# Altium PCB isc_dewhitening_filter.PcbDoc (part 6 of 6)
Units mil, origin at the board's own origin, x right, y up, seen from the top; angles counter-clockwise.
Board outline 8440 x 7000 mil, 6 copper layers (Top Layer, MidLayer1, InternalPlane1, Internal Plane 3, InternalPlane2, Bottom Layer); 550 components, 462 nets, 2189 pads, 795 vias.
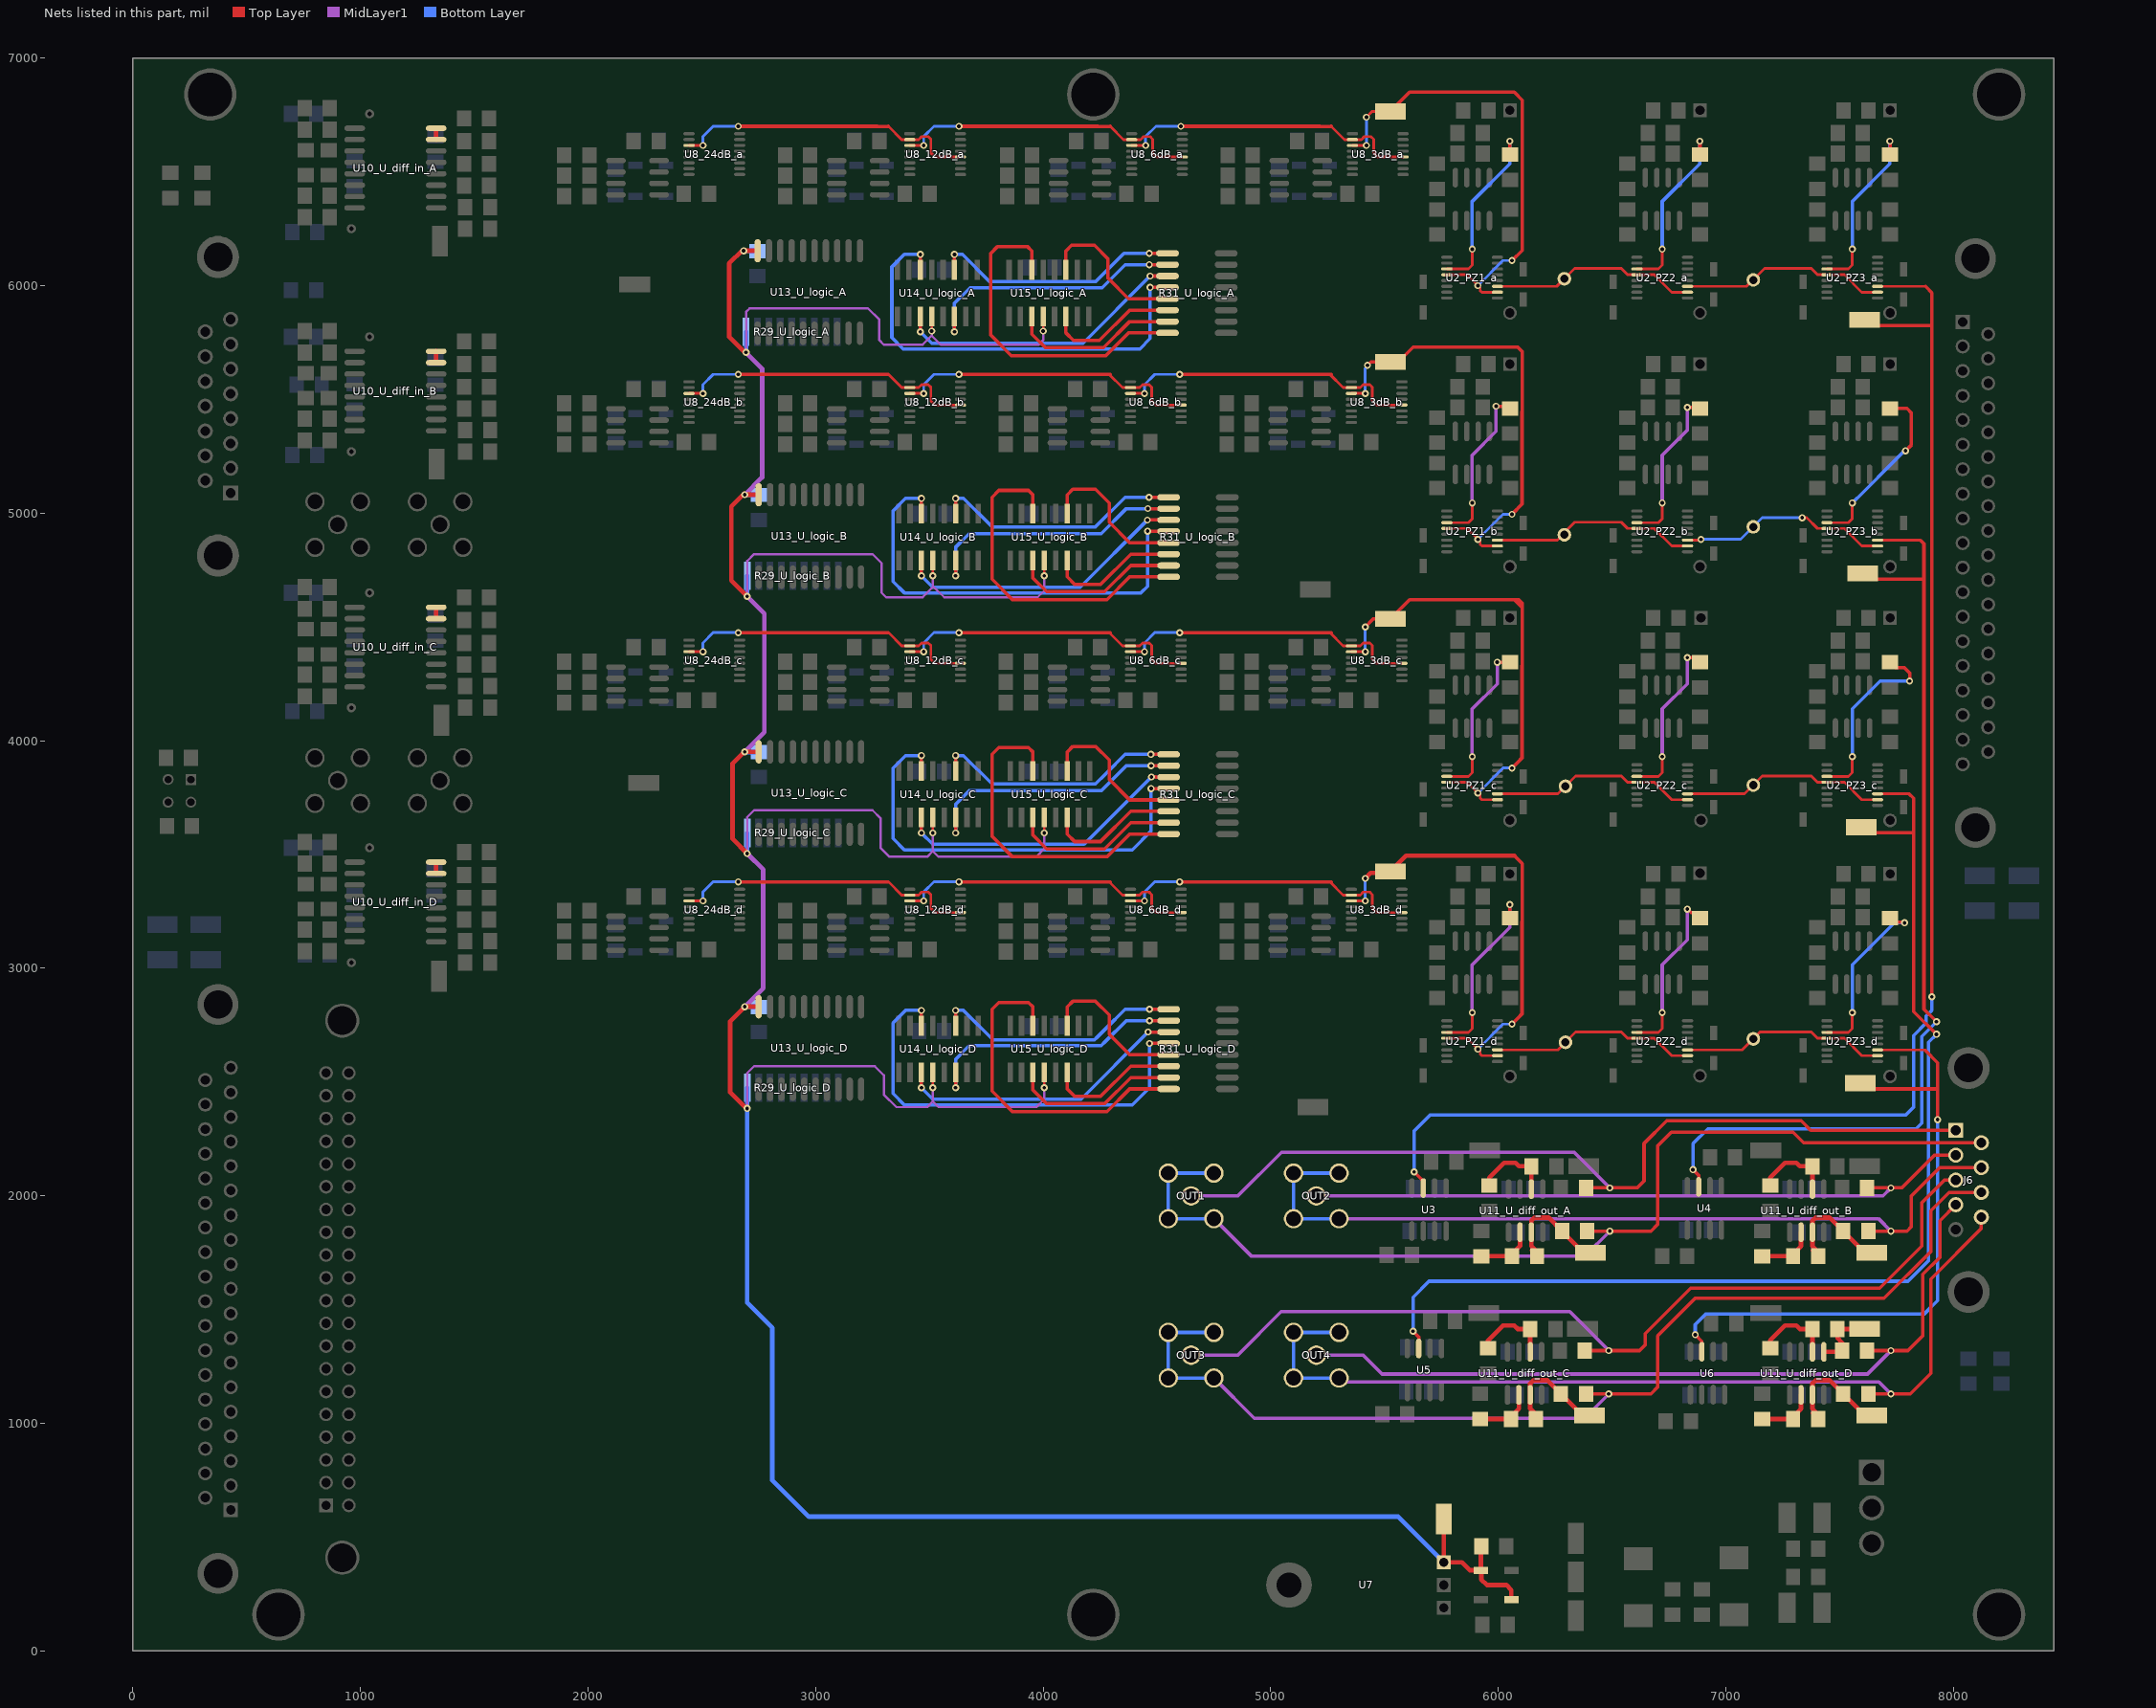
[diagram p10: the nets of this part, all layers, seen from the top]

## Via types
v1: diameter 31, hole 16, Top Layer to Bottom Layer, 794 vias
v2: diameter 45, hole 20, Top Layer to Bottom Layer, 1 vias

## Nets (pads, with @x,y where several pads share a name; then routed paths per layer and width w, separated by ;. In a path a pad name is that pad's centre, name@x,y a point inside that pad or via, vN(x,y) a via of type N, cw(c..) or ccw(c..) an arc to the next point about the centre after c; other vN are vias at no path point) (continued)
NetR23_U_diff_out_D_1: R23_U_diff_out_D.1 R25_U_diff_out_D.2 TP7_U_diff_out_D.1 U11_U_diff_out_D.1 | length 305.2
  Top Layer w15: R23_U_diff_out_D.1@7504.37,1314.49 R23_U_diff_out_D.1@7509.88,1320
  Top Layer w20: U11_U_diff_out_D.1@7430,1314.49 R23_U_diff_out_D.1@7504.37,1314.49 ; R23_U_diff_out_D.1@7509.88,1320 7509.88,1355.12 7490.12,1374.88 R25_U_diff_out_D.2@7490.12,1415 TP7_U_diff_out_D.1@7610,1415
NetR24_U_diff_out_A_2: R24_U_diff_out_A.2 R25_U_diff_out_A.1 U11_U_diff_out_A.2 | length 361.1
  Top Layer w20: R24_U_diff_out_A.2@5960,2045.12 5960,2080 6025,2145 6075,2145 6090,2130 R25_U_diff_out_A.1@6144.88,2130 R25_U_diff_out_A.1@6139.38,2135.5 ; U11_U_diff_out_A.2@6145,2029.49 R25_U_diff_out_A.1@6145,2129.88
NetR24_U_diff_out_B_2: R24_U_diff_out_B.2 R25_U_diff_out_B.1 U11_U_diff_out_B.2 | length 361.1
  Top Layer w20: R24_U_diff_out_B.2@7195,2045.12 7195,2080 7260,2145 7310,2145 7325,2130 R25_U_diff_out_B.1@7379.88,2130 R25_U_diff_out_B.1@7374.38,2135.5 ; U11_U_diff_out_B.2@7380,2029.49 R25_U_diff_out_B.1@7380,2129.88
NetR24_U_diff_out_C_2: R24_U_diff_out_C.2 R25_U_diff_out_C.1 U11_U_diff_out_C.2 | length 361.1
  Top Layer w20: R24_U_diff_out_C.2@5955,1330.12 5955,1365 6020,1430 6070,1430 6085,1415 R25_U_diff_out_C.1@6139.88,1415 R25_U_diff_out_C.1@6134.38,1420.5 ; U11_U_diff_out_C.2@6140,1314.49 R25_U_diff_out_C.1@6140,1414.88
NetR24_U_diff_out_D_2: R24_U_diff_out_D.2 R25_U_diff_out_D.1 U11_U_diff_out_D.2 | length 361.1
  Top Layer w20: R24_U_diff_out_D.2@7195,1330.12 7195,1365 7260,1430 7310,1430 7325,1415 R25_U_diff_out_D.1@7379.88,1415 R25_U_diff_out_D.1@7374.38,1420.5 ; U11_U_diff_out_D.2@7380,1314.49 R25_U_diff_out_D.1@7380,1414.88
NetR26_U_diff_out_A_1: R26_U_diff_out_A.1 R28_U_diff_out_A.2 TP9_U_diff_out_A.1 U11_U_diff_out_A.7 | length 531.2
  Top Layer w15: R28_U_diff_out_A.2@6145,1760.12 6170,1735.12 R28_U_diff_out_A.2@6170.12,1735
  Top Layer w20: R28_U_diff_out_A.2@6170,1735.12 6170,1755 6145,1780 U11_U_diff_out_A.7@6145,1840.51 6145,1890 6160,1905 6219.88,1905 R26_U_diff_out_A.1@6279.88,1845 6374.88,1750 TP9_U_diff_out_A.1@6405,1750
NetR26_U_diff_out_B_1: R26_U_diff_out_B.1 R28_U_diff_out_B.2 TP9_U_diff_out_B.1 U11_U_diff_out_B.7 | length 531.2
  Top Layer w15: R28_U_diff_out_B.2@7380,1760.12 7405,1735.12 R28_U_diff_out_B.2@7405.12,1735
  Top Layer w20: R28_U_diff_out_B.2@7405,1735.12 7405,1755 7380,1780 U11_U_diff_out_B.7@7380,1840.51 7380,1890 7395,1905 7454.88,1905 R26_U_diff_out_B.1@7514.88,1845 7609.88,1750 TP9_U_diff_out_B.1@7640,1750
NetR26_U_diff_out_C_1: R26_U_diff_out_C.1 R28_U_diff_out_C.2 TP9_U_diff_out_C.1 U11_U_diff_out_C.7 | length 531.2
  Top Layer w15: R28_U_diff_out_C.2@6140,1045.12 6165,1020.12 R28_U_diff_out_C.2@6165.12,1020
  Top Layer w20: R28_U_diff_out_C.2@6165,1020.12 6165,1040 6140,1065 U11_U_diff_out_C.7@6140,1125.51 6140,1175 6155,1190 6214.88,1190 R26_U_diff_out_C.1@6274.88,1130 6369.88,1035 TP9_U_diff_out_C.1@6400,1035
NetR26_U_diff_out_D_1: R26_U_diff_out_D.1 R28_U_diff_out_D.2 TP9_U_diff_out_D.1 U11_U_diff_out_D.7 | length 531.2
  Top Layer w15: R28_U_diff_out_D.2@7380,1045.12 7405,1020.12 R28_U_diff_out_D.2@7405.12,1020
  Top Layer w20: R28_U_diff_out_D.2@7405,1020.12 7405,1040 7380,1065 U11_U_diff_out_D.7@7380,1125.51 7380,1175 7395,1190 7454.88,1190 R26_U_diff_out_D.1@7514.88,1130 7609.88,1035 TP9_U_diff_out_D.1@7640,1035
NetR27_U_diff_out_A_2: R27_U_diff_out_A.2 R28_U_diff_out_A.1 U11_U_diff_out_A.6 | length 249.2
  Top Layer w20: R27_U_diff_out_A.2@5925,1734.88 6049.88,1734.88 6095,1780 U11_U_diff_out_A.6@6095,1840.51
NetR27_U_diff_out_B_2: R27_U_diff_out_B.2 R28_U_diff_out_B.1 U11_U_diff_out_B.6 | length 249.2
  Top Layer w20: R27_U_diff_out_B.2@7160,1734.88 7284.88,1734.88 7330,1780 U11_U_diff_out_B.6@7330,1840.51
NetR27_U_diff_out_C_2: R27_U_diff_out_C.2 R28_U_diff_out_C.1 U11_U_diff_out_C.6 | length 249.2
  Top Layer w20: R27_U_diff_out_C.2@5920,1019.88 6044.88,1019.88 6090,1065 U11_U_diff_out_C.6@6090,1125.51
NetR27_U_diff_out_D_2: R27_U_diff_out_D.2 R28_U_diff_out_D.1 U11_U_diff_out_D.6 | length 249.2
  Top Layer w20: R27_U_diff_out_D.2@7160,1019.88 7284.88,1019.88 7330,1065 U11_U_diff_out_D.6@7330,1125.51
NetR30_PZ1_a_2: R30_PZ1_a.2 U2_PZ1_a.3 | length 791.7
  Top Layer w12: U2_PZ1_a.3@5773.78,6073.39 5868.39,6073.39 5885,6090 v1(5885,6160)
  Top Layer w15: v1(6050,6635) 6051,6634 R30_PZ1_a.2@6051,6575.12
  Bottom Layer w15: v1(5885,6160) 5885,6370 6050,6535 v1(6050,6635)
NetR30_PZ1_b_2: R30_PZ1_b.2 U2_PZ1_b.3 | length 721.7
  Top Layer w12: U2_PZ1_b.3@5773.78,4958.39 5868.39,4958.39 5885,4975 v1(5885,5045)
  Top Layer w15: v1(5990,5470) 5990.54,5469.46 6041.66,5469.46 R30_PZ1_b.2@6051,5460.12
  MidLayer1 w15: v1(5885,5045) 5885,5255 5990,5360 v1(5990,5470)
NetR30_PZ1_c_2: R30_PZ1_c.2 U2_PZ1_c.3 | length 704.7
  Top Layer w12: U2_PZ1_c.3@5773.78,3843.39 5868.39,3843.39 5885,3860 v1(5885,3930)
  Top Layer w15: v1(5995,4345) 6050.88,4345 R30_PZ1_c.2@6051,4345.12
  MidLayer1 w15: v1(5885,3930) 5885,4140 5995,4250 v1(5995,4345)
NetR30_PZ1_d_2: R30_PZ1_d.2 U2_PZ1_d.3 | length 791.7
  Top Layer w12: U2_PZ1_d.3@5773.78,2718.39 5868.39,2718.39 5885,2735 v1(5885,2805)
  Top Layer w15: v1(6050,3280) 6051,3279 R30_PZ1_d.2@6051,3220.12
  MidLayer1 w15: v1(5885,2805) 5885,3015 6050,3180 v1(6050,3280)
NetR30_PZ2_a_2: R30_PZ2_a.2 U2_PZ2_a.3 | length 791.7
  Top Layer w12: U2_PZ2_a.3@6608.78,6073.39 6703.39,6073.39 6720,6090 v1(6720,6160)
  Top Layer w15: v1(6885,6635) 6886,6634 R30_PZ2_a.2@6886,6575.12
  Bottom Layer w15: v1(6720,6160) 6720,6370 6885,6535 v1(6885,6635)
NetR30_PZ2_b_2: R30_PZ2_b.2 U2_PZ2_b.3 | length 711.7
  Top Layer w12: U2_PZ2_b.3@6608.78,4958.39 6703.39,4958.39 6720,4975 v1(6720,5045)
  Top Layer w15: v1(6830,5465) 6881.12,5465 R30_PZ2_b.2@6886,5460.12
  MidLayer1 w15: v1(6720,5045) 6720,5255 6830,5365 v1(6830,5465)
NetR30_PZ2_c_2: R30_PZ2_c.2 U2_PZ2_c.3 | length 732.9
  Top Layer w12: U2_PZ2_c.3@6608.78,3843.39 6703.39,3843.39 6720,3860 v1(6720,3930)
  Top Layer w15: v1(6830,4365) 6866.12,4365 R30_PZ2_c.2@6886,4345.12
  MidLayer1 w15: v1(6720,3930) 6720,4140 6830,4250 v1(6830,4365)
NetR30_PZ2_d_2: R30_PZ2_d.2 U2_PZ2_d.3 | length 761.2
  Top Layer w12: U2_PZ2_d.3@6608.78,2718.39 6703.39,2718.39 6720,2735 v1(6720,2805)
  Top Layer w15: v1(6830,3260) 6830.9,3260 6846.79,3244.11 6862,3244.11 R30_PZ2_d.2@6886,3220.12
  MidLayer1 w15: v1(6720,2805) 6720,3015 6830,3125 v1(6830,3260)
NetR30_PZ3_a_2: R30_PZ3_a.2 U2_PZ3_a.3 | length 791.7
  Top Layer w12: U2_PZ3_a.3@7443.78,6073.39 7538.39,6073.39 7555,6090 v1(7555,6160)
  Top Layer w15: v1(7720,6635) 7721,6634 R30_PZ3_a.2@7721,6575.12
  Bottom Layer w15: v1(7555,6160) 7555,6370 7720,6535 v1(7720,6635)
NetR30_PZ3_b_2: R30_PZ3_b.2 U2_PZ3_b.3 | length 824.3
  Top Layer w12: U2_PZ3_b.3@7443.78,4958.39 7538.39,4958.39 7555,4975 v1(7555,5045)
  Top Layer w15: R30_PZ3_b.2@7721,5460.12 7794.88,5460.12 7815,5440 7815,5300 v1(7789,5274)
  Bottom Layer w15: 7575,5065 v1(7555,5045) 7776,5266 7776.67,5266 7784.67,5274 v1(7789,5274)
NetR30_PZ3_c_2: R30_PZ3_c.2 U2_PZ3_c.3 | length 842.2
  Top Layer w12: U2_PZ3_c.3@7443.78,3843.39 7538.39,3843.39 7555,3860 v1(7555,3930)
  Top Layer w15: R30_PZ3_c.2@7721,4345.12 7745,4321.12 7783.88,4321.12 7807,4298 v1(7807,4262)
  Bottom Layer w15: v1(7555,3930) 7555,4140 7677,4262 v1(7807,4262)
NetR30_PZ3_d_2: R30_PZ3_d.2 U2_PZ3_d.3 | length 777.1
  Top Layer w12: U2_PZ3_d.3@7443.78,2718.39 7538.39,2718.39 7555,2735 v1(7555,2805)
  Top Layer w15: R30_PZ3_d.2@7721,3220.12 7737.58,3203.54 7777.13,3203.54 7780.67,3200 v1(7785,3200)
  Bottom Layer w15: v1(7555,2805) 7555,3015 7740,3200 v1(7785,3200)
NetR31_U_logic_A_1: R31_U_logic_A.1 U14_U_logic_A.3 | length 1104.4
  Top Layer w15: U14_U_logic_A.3@3610,6069.36 v1(3610,6137) ; v1(4466,6142) R31_U_logic_A.1@4546.06,6142
  Bottom Layer w15: v1(3610,6137) 3645,6137 3764,6018 4231,6018 4355,6142 v1(4466,6142)
NetR31_U_logic_A_2: R31_U_logic_A.2 U14_U_logic_A.14 | length 1199.1
  Top Layer w15: v1(3610,5797) U14_U_logic_A.14@3610,5864.64 ; v1(4466,6092) R31_U_logic_A.2@4546.06,6092
  Bottom Layer w15: v1(3610,5797) 3610,5922 3678.43,5990.43 4258.43,5990.43 4360,6092 v1(4466,6092)
NetR31_U_logic_A_3: R31_U_logic_A.3 U14_U_logic_A.11 | length 1296.6
  Top Layer w15: v1(3460,5797) U14_U_logic_A.11@3460,5864.64 ; v1(4470,6042) R31_U_logic_A.3@4546.06,6042
  Bottom Layer w15: v1(3460,5797) 3510,5747 4175,5747 v1(4470,6042)
NetR31_U_logic_A_4: R31_U_logic_A.4 U14_U_logic_A.6 | length 2033.3
  Top Layer w15: U14_U_logic_A.6@3460,6069.36 v1(3460,6137) ; v1(4470,5992) R31_U_logic_A.4@4578.54,5992
  Bottom Layer w15: v1(3460,6137) 3390,6137 3335,6082 3335,5772 3385,5722 4425,5722 4470,5767 v1(4470,5992)
NetR31_U_logic_A_5: R31_U_logic_A.5 U15_U_logic_A.3 | length 718.7
  Top Layer w15: U15_U_logic_A.3@4100,6069.36 4100,6152 4125,6177 4225,6177 4285,6117 4285,6032 4375,5942 R31_U_logic_A.5@4578.54,5942
NetR31_U_logic_A_6: R31_U_logic_A.6 U15_U_logic_A.14 | length 619.9
  Top Layer w15: U15_U_logic_A.14@4100,5864.64 4100,5792 4133,5759 4247,5759 4380,5892 R31_U_logic_A.6@4578.54,5892
NetR31_U_logic_A_7: R31_U_logic_A.7 U15_U_logic_A.11 | length 778.7
  Top Layer w15: U15_U_logic_A.11@3950,5864.64 3950,5787 4010,5727 4265,5727 4380,5842 R31_U_logic_A.7@4578.54,5842
NetR31_U_logic_A_8: R31_U_logic_A.8 U15_U_logic_A.6 | length 1530.6
  Top Layer w15: U15_U_logic_A.6@3950,6069.36 3950,6152 3930,6172 3830,6172 3800,6172 3770,6142 3770,5782 3860,5692 4275,5692 4375,5792 R31_U_logic_A.8@4578.54,5792
NetR31_U_logic_B_1: R31_U_logic_B.1 U14_U_logic_B.3 | length 1104.3
  Top Layer w15: U14_U_logic_B.3@3615,4997.36 v1(3615,5065) ; v1(4465,5070) R31_U_logic_B.1@4551.06,5070
  Bottom Layer w15: v1(3615,5065) 3650,5065 3775,4940 4230,4940 4360,5070 v1@4460,5070
NetR31_U_logic_B_2: R31_U_logic_B.2 U14_U_logic_B.14 | length 1199.1
  Top Layer w15: v1(3615,4725) U14_U_logic_B.14@3615,4792.64 ; v1(4460,5020) R31_U_logic_B.2@4551.06,5020
  Bottom Layer w15: v1(3615,4725) 3615,4850 3675,4910 4255,4910 4365,5020 v1(4460,5020)
NetR31_U_logic_B_3: R31_U_logic_B.3 U14_U_logic_B.11 | length 1329.1
  Top Layer w15: v1(3465,4725) U14_U_logic_B.11@3465,4792.64 ; v1(4458,4970) R31_U_logic_B.3@4583.54,4970
  Bottom Layer w15: v1(3465,4725) 3515,4675 4163,4675 v1(4458,4970)
NetR31_U_logic_B_4: R31_U_logic_B.4 U14_U_logic_B.6 | length 2043.7
  Top Layer w15: U14_U_logic_B.6@3465,4997.36 v1(3465,5065) ; v1@4459,4920 R31_U_logic_B.4@4583.54,4920
  Bottom Layer w15: v1(3465,5065) 3395,5065 3340,5010 3340,4700 3390,4650 4430,4650 4459,4679 v1(4459,4921)
NetR31_U_logic_B_5: R31_U_logic_B.5 U15_U_logic_B.3 | length 718.7
  Top Layer w15: U15_U_logic_B.3@4105,4997.36 4105,5080 4130,5105 4230,5105 4290,5045 4290,4960 4380,4870 R31_U_logic_B.5@4583.54,4870
NetR31_U_logic_B_6: R31_U_logic_B.6 U15_U_logic_B.14 | length 619.9
  Top Layer w15: U15_U_logic_B.14@4105,4792.64 4105,4720 4138,4687 4252,4687 4385,4820 R31_U_logic_B.6@4583.54,4820
NetR31_U_logic_B_7: R31_U_logic_B.7 U15_U_logic_B.11 | length 778.7
  Top Layer w15: U15_U_logic_B.11@3955,4792.64 3955,4715 4015,4655 4270,4655 4385,4770 R31_U_logic_B.7@4583.54,4770
NetR31_U_logic_B_8: R31_U_logic_B.8 U15_U_logic_B.6 | length 1530.6
  Top Layer w15: U15_U_logic_B.6@3955,4997.36 3955,5080 3935,5100 3835,5100 3805,5100 3775,5070 3775,4710 3865,4620 4280,4620 4380,4720 R31_U_logic_B.8@4583.54,4720
NetR31_U_logic_C_1: R31_U_logic_C.1 U14_U_logic_C.3 | length 1141.8
  Top Layer w15: U14_U_logic_C.3@3615,3867.36 v1(3615,3935) ; v1(4473,3940) R31_U_logic_C.1@4583.54,3940
  Bottom Layer w15: v1(3615,3935) 3650,3935 3775,3810 4230,3810 4275,3855 4360,3940 v1(4473,3940)
NetR31_U_logic_C_2: R31_U_logic_C.2 U14_U_logic_C.14 | length 1231.6
  Top Layer w15: v1(3615,3595) U14_U_logic_C.14@3615,3662.64 ; v1(4474,3890) R31_U_logic_C.2@4583.54,3890
  Bottom Layer w15: v1(3615,3595) 3615,3720 3675,3780 4255,3780 4273,3798 4365,3890 v1(4474,3890)
NetR31_U_logic_C_3: R31_U_logic_C.3 U14_U_logic_C.11 | length 1329.9
  Top Layer w15: v1(3465,3595) U14_U_logic_C.11@3465,3662.64 ; v1(4476,3841) 4494,3841 4495,3840 R31_U_logic_C.3@4583.54,3840
  Bottom Layer w15: v1(3465,3595) 3515,3545 4180,3545 v1(4476,3841)
NetR31_U_logic_C_4: R31_U_logic_C.4 U14_U_logic_C.6 | length 2011.1
  Top Layer w15: U14_U_logic_C.6@3465,3867.36 v1(3465,3935) ; v1(4474,3790) R31_U_logic_C.4@4583.54,3790
  Bottom Layer w15: v1(3465,3935) 3395,3935 3340,3880 3340,3570 3390,3520 4391,3520 4474,3603 v1(4474,3790)
NetR31_U_logic_C_5: R31_U_logic_C.5 U15_U_logic_C.3 | length 718.7
  Top Layer w15: U15_U_logic_C.3@4105,3867.36 4105,3950 4130,3975 4230,3975 4290,3915 4290,3830 4380,3740 R31_U_logic_C.5@4583.54,3740
NetR31_U_logic_C_6: R31_U_logic_C.6 U15_U_logic_C.14 | length 619.9
  Top Layer w15: U15_U_logic_C.14@4105,3662.64 4105,3590 4138,3557 4252,3557 4385,3690 R31_U_logic_C.6@4583.54,3690
NetR31_U_logic_C_7: R31_U_logic_C.7 U15_U_logic_C.11 | length 778.7
  Top Layer w15: U15_U_logic_C.11@3955,3662.64 3955,3585 4015,3525 4270,3525 4385,3640 R31_U_logic_C.7@4583.54,3640
NetR31_U_logic_C_8: R31_U_logic_C.8 U15_U_logic_C.6 | length 1530.6
  Top Layer w15: U15_U_logic_C.6@3955,3867.36 3955,3950 3935,3970 3835,3970 3805,3970 3775,3940 3775,3580 3865,3490 4280,3490 4380,3590 R31_U_logic_C.8@4583.54,3590
NetR31_U_logic_D_1: R31_U_logic_D.1 U14_U_logic_D.3 | length 1145.9
  Top Layer w15: U14_U_logic_D.3@3615,2747.36 v1(3615,2815) ; v1(4467,2820) R31_U_logic_D.1@4583.54,2820
  Bottom Layer w15: v1(3615,2815) 3650,2815 3780,2685 4225,2685 4235,2695 4275,2735 4360,2820 v1(4467,2820)
NetR31_U_logic_D_2: R31_U_logic_D.2 U14_U_logic_D.14 | length 1231.6
  Top Layer w15: v1(3615,2475) U14_U_logic_D.14@3615,2542.64 ; v1(4467,2770) R31_U_logic_D.2@4583.54,2770
  Bottom Layer w15: v1(3615,2475) 3615,2600 3675,2660 4255,2660 4273,2678 4365,2770 v1(4467,2770)
NetR31_U_logic_D_3: R31_U_logic_D.3 U14_U_logic_D.11 | length 1329.1
  Top Layer w15: v1(3465,2475) U14_U_logic_D.11@3465,2542.64 ; v1(4461,2720) R31_U_logic_D.3@4583.54,2720
  Bottom Layer w15: v1(3465,2475) 3515,2425 4166,2425 v1(4461,2720)
NetR31_U_logic_D_4: R31_U_logic_D.4 U14_U_logic_D.6 | length 1983.3
  Top Layer w15: U14_U_logic_D.6@3465,2747.36 v1(3465,2815) ; v1(4467,2670) R31_U_logic_D.4@4551.06,2670
  Bottom Layer w15: v1(3465,2815) 3395,2815 3340,2760 3340,2450 3390,2400 4392,2400 4467,2475 v1(4467,2670)
NetR31_U_logic_D_5: R31_U_logic_D.5 U15_U_logic_D.3 | length 718.7
  Top Layer w15: U15_U_logic_D.3@4105,2747.36 4105,2830 4130,2855 4230,2855 4290,2795 4290,2710 4380,2620 R31_U_logic_D.5@4583.54,2620
NetR31_U_logic_D_6: R31_U_logic_D.6 U15_U_logic_D.14 | length 619.9
  Top Layer w15: U15_U_logic_D.14@4105,2542.64 4105,2470 4138,2437 4252,2437 4385,2570 R31_U_logic_D.6@4583.54,2570
NetR31_U_logic_D_7: R31_U_logic_D.7 U15_U_logic_D.11 | length 778.7
  Top Layer w15: U15_U_logic_D.11@3955,2542.64 3955,2465 4015,2405 4270,2405 4385,2520 R31_U_logic_D.7@4583.54,2520
NetR31_U_logic_D_8: R31_U_logic_D.8 U15_U_logic_D.6 | length 1530.6
  Top Layer w15: U15_U_logic_D.6@3955,2747.36 3955,2830 3935,2850 3835,2850 3805,2850 3775,2820 3775,2460 3865,2370 4280,2370 4380,2470 R31_U_logic_D.8@4583.54,2470
NetTP2_1: TP2.1 U2_PZ1_a.4 U2_PZ1_a.10 U8_3dB_a.11 | length 2110.5
  Top Layer w12: U8_3dB_a.11@5358.78,6616.18 v1(5420,6616.18) ; v1(5420,6740) 5445,6765 TP2.1@5525,6765 ; U2_PZ1_a.4@5773.78,6047.8 5862.2,6047.8 v1(5910,6000) 5920,5990 5920,5978.05 5927.03,5971.02 U2_PZ1_a.10@5996.22,5971.02
  Top Layer w15: TP2.1@5525,6765 5610,6850 6070,6850 6105,6815 6105,6155 v1(6060,6110)
  Bottom Layer w12: v1(5420,6616.18) v1(5420,6740) ; v1(5910,6000) 6020,6110 v1(6060,6110)
NetTP13_1: TP13.1 U2_PZ3_a.11 U3.3 | length 6672.8
  Top Layer w12: U2_PZ3_a.11@7666.22,5996.61 7876.61,5996.61
  Top Layer w15: v1(5630,2105) 5670,2065 U3.3@5670,2034.49 ; TP13.1@7610,5850 7635,5825 7905,5825 ; 7876.61,5996.61 7905,5968.23 7905,5825.3 v1(7905,2875)
  Bottom Layer w15: v1(5630,2105) 5630,2285 5700,2355 7790,2355 7825,2390 7825,2705 7880,2760 7880,2790 7905,2815 v1(7905,2875)
NetTP15_1: TP15.1 U2_PZ1_b.4 U2_PZ1_b.10 U8_3dB_b.11 | length 2758.1
  Top Layer w12: U8_3dB_b.11@5353.78,5526.18 v1(5415,5526.18) ; U2_PZ1_b.4@5773.78,4932.8 5862.2,4932.8 v1(5910,4885) 5920,4875 5920,4863.05 5927.03,4856.02 U2_PZ1_b.10@5996.22,4856.02
  Top Layer w15: v1(5425,5650) 5426.18,5650 5441.18,5665 TP15.1@5525,5665 5560,5665 5625,5730 6085,5730 6105,5710 6105,5476.24 ; v1(6060,4995) 6105,5040 6105,5700 ; 6084,5020 6104,5040 6104,5445
  Bottom Layer w12: v1(5415,5526.18) 5415,5634.86 5425,5644.86 v1(5425,5650) ; v1(5910,4885) 6020,4995 v1(6060,4995)
NetTP16_1: TP16.1 U2_PZ3_b.11 U4.3 | length 4323.2
  Top Layer w12: U2_PZ3_b.11@7666.22,4881.61 7855,4881.61
  Top Layer w15: v1@6860,2115 v1(6855,2115) 6880,2090 U4.3@6880,2039.49 ; TP16.1@7610,4735 7635,4710 7870,4710 ; 7855,4880 7870,4865 7870,4710 ; v1(7925,2765) 7870,2820 7870,3766.61 7870,4710
  Bottom Layer w15: v1(6855,2115) 6855,2230 6920,2295 7835,2295 7860,2320 7860,2700 v1(7925,2765)
NetTP18_1: TP18.1 U2_PZ1_c.4 U2_PZ1_c.10 U8_3dB_c.11 | length 2814.2
  Top Layer w12: U8_3dB_c.11@5353.78,4391.18 v1(5415,4391.18) ; U2_PZ1_c.4@5773.78,3817.8 5862.2,3817.8 v1(5910,3770) 5920,3760 5920,3748.05 5927.03,3741.02 U2_PZ1_c.10@5996.22,3741.02
  Top Layer w15: v1(5415,4500) 5450,4535 TP18.1@5525,4535 5610,4620 6090,4620 6105,4605 6105,4370 ; v1(6060,3880) 6105,3925 6105,4585 6070,4620 ; 6084,3905 6104,3925 6104,4330
  Bottom Layer w12: v1(5415,4391.18) v1(5415,4500) ; v1(5910,3770) 6020,3880 v1(6060,3880)
NetTP19_1: TP19.1 U2_PZ3_c.11 U5.3 | length 5047.1
  Top Layer w12: U2_PZ3_c.11@7666.22,3766.61 7805,3766.61
  Top Layer w15: v1(5625,1405) 5650,1380 U5.3@5650,1329.49 ; TP19.1@7610,3620 7635,3595 7825,3595 ; 7805,3766.61 7825,3746.61 7825,3595 ; v1(7925,2710) 7825,2810 7825,3595
  Bottom Layer w15: v1(5625,1405) 5625,1555 5695,1625 7800,1625 7890,1715 7890,2675 v1(7925,2710)
NetTP21_1: TP21.1 U2_PZ1_d.4 U2_PZ1_d.10 U8_3dB_d.11 | length 2519.7
  Top Layer w12: U8_3dB_d.11@5353.78,3296.18 v1(5415,3296.18) ; U2_PZ1_d.4@5773.78,2692.8 5862.2,2692.8 v1(5910,2645) 5920,2635 5920,2623.05 5927.03,2616.02 U2_PZ1_d.10@5996.22,2616.02
  Top Layer w15: v1(6060,2755) 6105,2800 6105,3460 6070,3495 ; 6084,2780 6104,2800 6104,3205
  Top Layer w20: v1(5415,3395) 5439.22,3419.22 5519.22,3419.22 TP21.1@5525,3425 5595,3495 6070,3495
  Bottom Layer w12: v1(5415,3296.18) v1(5415,3395) ; v1(5910,2645) 6020,2755 v1(6060,2755)
NetTP22_1: TP22.1 U2_PZ3_d.11 U6.3 | length 2898.5
  Top Layer w12: U2_PZ3_d.11@7666.22,2641.61 7871.61,2641.61
  Top Layer w15: v1(6865,1390) 6894,1361 U6.3@6894,1315.49 ; TP22.1@7610,2495 7635,2470 7930,2470 ; 7875,2640 7930,2585 7930,2470 ; v1(7930,2335) 7930,2470
  Bottom Layer w15: v1(6865,1390) 6865,1435 6910,1480 7870,1480 7930,1540 v1(7930,2335)
NetU2_PZ2_a_4: pad.0@6290,6030 U2_PZ1_a.11 U2_PZ2_a.4 U2_PZ2_a.10 | length 910.5
  Top Layer w12: U2_PZ1_a.11@5996.22,5996.61 6256.61,5996.61 pad.0@6290,6030 6335,6075 6540,6075 6567.2,6047.8 U2_PZ2_a.4@6608.78,6047.8 6685.26,6047.8 6762.03,5971.02 U2_PZ2_a.10@6831.22,5971.02
NetU2_PZ2_b_4: pad.2 U2_PZ1_b.11 U2_PZ2_b.4 U2_PZ2_b.10 | length 916.4
  Top Layer w12: U2_PZ1_b.11@5996.22,4881.61 6258.97,4881.61 6282.36,4905 pad.2@6290,4905 6290,4915 6335,4960 6540,4960 6567.2,4932.8 U2_PZ2_b.4@6608.78,4932.8 6685.26,4932.8 6762.03,4856.02 U2_PZ2_b.10@6831.22,4856.02
NetU2_PZ2_c_4: pad.3 U2_PZ1_c.11 U2_PZ2_c.4 U2_PZ2_c.10 | length 935.5
  Top Layer w12: U2_PZ1_c.11@5996.22,3766.61 6261.61,3766.61 pad.3@6295,3800 6340,3845 ; 6365,3845 6340,3845 ; U2_PZ2_c.10@6831.22,3741.02 6762.03,3741.02 6685.26,3817.8 U2_PZ2_c.4@6608.78,3817.8 6567.2,3817.8 6540,3845 6340,3845
NetU2_PZ2_d_4: pad.4 U2_PZ1_d.11 U2_PZ2_d.4 U2_PZ2_d.10 | length 910.5
  Top Layer w12: U2_PZ1_d.11@5996.22,2641.61 6261.61,2641.61 pad.4@6295,2675 6340,2720 6540,2720 6567.2,2692.8 U2_PZ2_d.4@6608.78,2692.8 6685.26,2692.8 6762.03,2616.02 U2_PZ2_d.10@6831.22,2616.02
NetU2_PZ3_a_4: pad.1@7120,6025 U2_PZ2_a.11 U2_PZ3_a.4 U2_PZ3_a.10 | length 910.5
  Top Layer w12: U2_PZ2_a.11@6831.22,5996.61 7090.44,5996.61 7118.83,6025 pad.1@7120,6025 7170,6075 7375,6075 7402.2,6047.8 U2_PZ3_a.4@7443.78,6047.8 7520.26,6047.8 7597.03,5971.02 U2_PZ3_a.10@7666.22,5971.02
NetU2_PZ3_b_4: pad.5@7120,4940 U2_PZ2_b.11 U2_PZ3_b.4 U2_PZ3_b.10 | length 927.1
  Top Layer w12: U2_PZ2_b.11@6831.22,4881.61 6886.61,4881.61 v1(6890,4885) ; v1(7335,4980) 7355,4980 7402.2,4932.8 U2_PZ3_b.4@7443.78,4932.8 7520.26,4932.8 7597.03,4856.02 U2_PZ3_b.10@7666.22,4856.02
  Bottom Layer w12: v1(6890,4885) 7065,4885 pad.5@7120,4940 7160,4980 v1(7335,4980)
NetU2_PZ3_c_4: pad.6@7120,3805 U2_PZ2_c.11 U2_PZ3_c.4 U2_PZ3_c.10 | length 910.5
  Top Layer w12: U2_PZ2_c.11@6831.22,3766.61 7081.61,3766.61 pad.6@7120,3805 7160,3845 7375,3845 7402.2,3817.8 U2_PZ3_c.4@7443.78,3817.8 7520.26,3817.8 7597.03,3741.02 U2_PZ3_c.10@7666.22,3741.02
NetU2_PZ3_d_4: pad.7@7120,2690 U2_PZ2_d.11 U2_PZ3_d.4 U2_PZ3_d.10 | length 910.5
  Top Layer w12: U2_PZ2_d.11@6831.22,2641.61 7071.61,2641.61 pad.7@7120,2690 7150,2720 7375,2720 7402.2,2692.8 U2_PZ3_d.4@7443.78,2692.8 7520.26,2692.8 7597.03,2616.02 U2_PZ3_d.10@7666.22,2616.02
NetU8_3dB_a_4: U8_3dB_a.4 U8_3dB_a.10 U8_6dB_a.11 | length 3796
  Top Layer w12: U8_6dB_a.11@4388.78,6616.18 v1(4450,6616.18) ; 5265,6700 5323.23,6641.77 U8_3dB_a.10@5358.78,6641.77 5398.23,6641.77 5411.46,6655 5440,6655 5451.5,6643.5 5451.5,6583.5 5470,6565 U8_3dB_a.4@5581.22,6565
  Top Layer w15: v1@4600.88,6699.12 5265,6700 ; v1(4605,6700) 5215,6700 ; v1@4600,6700 5210,6700 ; v1@4600,6700 5210,6700 ; v1@4600,6700 5210,6700
  Bottom Layer w12: v1(4450,6616.18) 4450,6655 4495,6700 v1(4605,6700)
NetU8_3dB_b_4: U8_3dB_b.4 U8_3dB_b.10 U8_6dB_b.11 | length 6900.2
  Top Layer w12: U8_6dB_b.11@4383.78,5526.18 v1(4445,5526.18) ; 5260,5610 5318.23,5551.77 U8_3dB_b.10@5353.78,5551.77 5393.23,5551.77 5406.46,5565 5435,5565 5446.5,5553.5 5446.5,5493.5 5465,5475 U8_3dB_b.4@5576.22,5475
  Top Layer w15: v1@4595.88,5609.12 5260,5610 ; v1@4600.88,5609.12 5265,5610 ; v1@4595,5610 5205,5610 ; v1@4595,5610 5205,5610 ; v1@4595,5610 5205,5610 ; v1(4600,5610) 5210,5610 ; v1(4600,5610) 5210,5610 ; v1(4600,5610) 5210,5610 ; v1(4600,5610) 5210,5610 ; v1(4600,5610) 5210,5610
  Bottom Layer w12: v1(4445,5526.18) 4445,5565 4490,5610 v1(4600,5610)
NetU8_3dB_c_4: U8_3dB_c.4 U8_3dB_c.10 U8_6dB_c.11 | length 6900.2
  Top Layer w12: U8_6dB_c.11@4383.78,4391.18 v1(4445,4391.18) ; 5260,4475 5318.23,4416.77 U8_3dB_c.10@5353.78,4416.77 5393.23,4416.77 5406.46,4430 5435,4430 5446.5,4418.5 5446.5,4358.5 5465,4340 U8_3dB_c.4@5576.22,4340
  Top Layer w15: v1@4595.88,4474.12 5260,4475 ; v1@4600.88,4474.12 5265,4475 ; v1@4595,4475 5205,4475 ; v1@4595,4475 5205,4475 ; v1@4595,4475 5205,4475 ; v1(4600,4475) 5210,4475 ; v1(4600,4475) 5210,4475 ; v1(4600,4475) 5210,4475 ; v1(4600,4475) 5210,4475 ; v1(4600,4475) 5210,4475
  Bottom Layer w12: v1(4445,4391.18) 4445,4430 4490,4475 v1(4600,4475)
NetU8_3dB_d_4: U8_3dB_d.4 U8_3dB_d.10 U8_6dB_d.11 | length 6900.2
  Top Layer w12: U8_6dB_d.11@4383.78,3296.18 v1(4445,3296.18) ; 5260,3380 5318.23,3321.77 U8_3dB_d.10@5353.78,3321.77 5393.23,3321.77 5406.46,3335 5435,3335 5446.5,3323.5 5446.5,3263.5 5465,3245 U8_3dB_d.4@5576.22,3245
  Top Layer w15: v1@4595.88,3379.12 5260,3380 ; v1@4600.88,3379.12 5265,3380 ; v1@4595,3380 5205,3380 ; v1@4595,3380 5205,3380 ; v1@4595,3380 5205,3380 ; v1(4600,3380) 5210,3380 ; v1(4600,3380) 5210,3380 ; v1(4600,3380) 5210,3380 ; v1(4600,3380) 5210,3380 ; v1(4600,3380) 5210,3380
  Bottom Layer w12: v1(4445,3296.18) 4445,3335 4490,3380 v1(4600,3380)
NetU8_6dB_a_4: U8_6dB_a.4 U8_6dB_a.10 U8_12dB_a.11 | length 3796
  Top Layer w12: U8_12dB_a.11@3413.78,6616.18 v1(3475,6616.18) ; 4295,6700 4353.23,6641.77 U8_6dB_a.10@4388.78,6641.77 4428.23,6641.77 4441.46,6655 4470,6655 4481.5,6643.5 4481.5,6583.5 4500,6565 U8_6dB_a.4@4611.22,6565
  Top Layer w15: v1@3630.88,6699.12 4295,6700 ; v1(3630,6700) 4240,6700 ; v1(3630,6700) 4240,6700 ; v1(3630,6700) 4240,6700 ; v1(3630,6700) 4240,6700
  Bottom Layer w12: v1(3475,6616.18) 3475,6655 3520,6700 v1(3630,6700)
NetU8_6dB_b_4: U8_6dB_b.4 U8_6dB_b.10 U8_12dB_b.11 | length 6900.2
  Top Layer w12: U8_12dB_b.11@3413.78,5526.18 v1(3475,5526.18) ; 4290,5610 4348.23,5551.77 U8_6dB_b.10@4383.78,5551.77 4423.23,5551.77 4436.46,5565 4465,5565 4476.5,5553.5 4476.5,5493.5 4495,5475 U8_6dB_b.4@4606.22,5475
  Top Layer w15: v1@3625.88,5609.12 4290,5610 ; v1@3630.88,5609.12 4295,5610 ; v1@3625,5610 4235,5610 ; v1@3625,5610 4235,5610 ; v1@3625,5610 4235,5610 ; v1(3630,5610) 4240,5610 ; v1(3630,5610) 4240,5610 ; v1(3630,5610) 4240,5610 ; v1(3630,5610) 4240,5610 ; v1(3630,5610) 4240,5610
  Bottom Layer w12: v1(3475,5526.18) 3475,5565 3520,5610 v1(3630,5610)
NetU8_6dB_c_4: U8_6dB_c.4 U8_6dB_c.10 U8_12dB_c.11 | length 6900.2
  Top Layer w12: U8_12dB_c.11@3413.78,4391.18 v1(3475,4391.18) ; 4290,4475 4348.23,4416.77 U8_6dB_c.10@4383.78,4416.77 4423.23,4416.77 4436.46,4430 4465,4430 4476.5,4418.5 4476.5,4358.5 4495,4340 U8_6dB_c.4@4606.22,4340
  Top Layer w15: v1@3625.88,4474.12 4290,4475 ; v1@3630.88,4474.12 4295,4475 ; v1@3625,4475 4235,4475 ; v1@3625,4475 4235,4475 ; v1@3625,4475 4235,4475 ; v1(3630,4475) 4240,4475 ; v1(3630,4475) 4240,4475 ; v1(3630,4475) 4240,4475 ; v1(3630,4475) 4240,4475 ; v1(3630,4475) 4240,4475
  Bottom Layer w12: v1(3475,4391.18) 3475,4430 3520,4475 v1(3630,4475)
NetU8_6dB_d_4: U8_6dB_d.4 U8_6dB_d.10 U8_12dB_d.11 | length 6900.2
  Top Layer w12: U8_12dB_d.11@3413.78,3296.18 v1(3475,3296.18) ; 4290,3380 4348.23,3321.77 U8_6dB_d.10@4383.78,3321.77 4423.23,3321.77 4436.46,3335 4465,3335 4476.5,3323.5 4476.5,3263.5 4495,3245 U8_6dB_d.4@4606.22,3245
  Top Layer w15: v1@3625.88,3379.12 4290,3380 ; v1@3630.88,3379.12 4295,3380 ; v1@3625,3380 4235,3380 ; v1@3625,3380 4235,3380 ; v1@3625,3380 4235,3380 ; v1(3630,3380) 4240,3380 ; v1(3630,3380) 4240,3380 ; v1(3630,3380) 4240,3380 ; v1(3630,3380) 4240,3380 ; v1(3630,3380) 4240,3380
  Bottom Layer w12: v1(3475,3296.18) 3475,3335 3520,3380 v1(3630,3380)
NetU8_12dB_a_4: U8_12dB_a.4 U8_12dB_a.10 U8_24dB_a.11 | length 3796
  Top Layer w12: U8_24dB_a.11@2443.78,6616.18 v1(2505,6616.18) ; 3320,6700 3378.23,6641.77 U8_12dB_a.10@3413.78,6641.77 3453.23,6641.77 3466.46,6655 3495,6655 3506.5,6643.5 3506.5,6583.5 3525,6565 U8_12dB_a.4@3636.22,6565
  Top Layer w15: v1@2655.88,6699.12 3320,6700 ; v1(2660,6700) 3270,6700 ; v1@2655,6700 3265,6700 ; v1@2655,6700 3265,6700 ; v1@2655,6700 3265,6700
  Bottom Layer w12: v1(2505,6616.18) 2505,6655 2550,6700 v1(2660,6700)
NetU8_12dB_b_4: U8_12dB_b.4 U8_12dB_b.10 U8_24dB_b.11 | length 6900.2
  Top Layer w12: U8_24dB_b.11@2443.78,5526.18 v1(2505,5526.18) ; 3320,5610 3378.23,5551.77 U8_12dB_b.10@3413.78,5551.77 3453.23,5551.77 3466.46,5565 3495,5565 3506.5,5553.5 3506.5,5493.5 3525,5475 U8_12dB_b.4@3636.22,5475
  Top Layer w15: v1@2655,5610 3265,5610 ; v1@2655,5610 3265,5610 ; v1@2655,5610 3265,5610 ; v1@2655,5610 3265,5610 ; v1@2655,5610 3265,5610 ; v1@2655,5610 3265,5610 ; v1@2655.88,5609.12 3320,5610 v1@2655.88,5609.12 ; v1(2660,5610) 3270,5610 v1(2660,5610)
  Bottom Layer w12: v1(2505,5526.18) 2505,5565 2550,5610 v1(2660,5610)
NetU8_12dB_c_4: U8_12dB_c.4 U8_12dB_c.10 U8_24dB_c.11 | length 6900.2
  Top Layer w12: U8_24dB_c.11@2443.78,4391.18 v1(2505,4391.18) ; 3320,4475 3378.23,4416.77 U8_12dB_c.10@3413.78,4416.77 3453.23,4416.77 3466.46,4430 3495,4430 3506.5,4418.5 3506.5,4358.5 3525,4340 U8_12dB_c.4@3636.22,4340
  Top Layer w15: v1@2655,4475 3265,4475 ; v1@2655,4475 3265,4475 ; v1@2655,4475 3265,4475 ; v1@2655,4475 3265,4475 ; v1@2655,4475 3265,4475 ; v1@2655,4475 3265,4475 ; v1@2655.88,4474.12 3320,4475 v1@2655.88,4474.12 ; v1(2660,4475) 3270,4475 v1(2660,4475)
  Bottom Layer w12: v1(2505,4391.18) 2505,4430 2550,4475 v1(2660,4475)
NetU8_12dB_d_4: U8_12dB_d.4 U8_12dB_d.10 U8_24dB_d.11 | length 6900.2
  Top Layer w12: U8_24dB_d.11@2443.78,3296.18 v1(2505,3296.18) ; 3320,3380 3378.23,3321.77 U8_12dB_d.10@3413.78,3321.77 3453.23,3321.77 3466.46,3335 3495,3335 3506.5,3323.5 3506.5,3263.5 3525,3245 U8_12dB_d.4@3636.22,3245
  Top Layer w15: v1@2655,3380 3265,3380 ; v1@2655,3380 3265,3380 ; v1@2655,3380 3265,3380 ; v1@2655,3380 3265,3380 ; v1@2655,3380 3265,3380 ; v1@2655,3380 3265,3380 ; v1@2655.88,3379.12 3320,3380 v1@2655.88,3379.12 ; v1(2660,3380) 3270,3380 v1(2660,3380)
  Bottom Layer w12: v1(2505,3296.18) 2505,3335 2550,3380 v1(2660,3380)
NetU10_U_diff_in_A_15: U10_U_diff_in_A.15 U10_U_diff_in_A.16 | length 50
  Top Layer w20: U10_U_diff_in_A.15@1332.8,6641.5 U10_U_diff_in_A.16@1332.8,6691.5
NetU10_U_diff_in_B_15: U10_U_diff_in_B.15 U10_U_diff_in_B.16 | length 50
  Top Layer w20: U10_U_diff_in_B.15@1332.8,5661.5 U10_U_diff_in_B.16@1332.8,5711.5
NetU10_U_diff_in_C_15: U10_U_diff_in_C.15 U10_U_diff_in_C.16 | length 50
  Top Layer w20: U10_U_diff_in_C.15@1332.8,4536.5 U10_U_diff_in_C.16@1332.8,4586.5
NetU10_U_diff_in_D_15: U10_U_diff_in_D.15 U10_U_diff_in_D.16 | length 50
  Top Layer w20: U10_U_diff_in_D.15@1332.8,3416.5 U10_U_diff_in_D.16@1332.8,3466.5
VCC: C21.2 C33_U_logic_A.2 C33_U_logic_B.2 C33_U_logic_C.2 C33_U_logic_D.2 D3.1 D5.2 R29_U_logic_A.1 R29_U_logic_B.1 R29_U_logic_C.1 R29_U_logic_D.1 TP5.1 U7.3 U13_U_logic_A.20 U13_U_logic_B.20 U13_U_logic_C.20 U13_U_logic_D.20 U14_U_logic_A.12 U14_U_logic_B.12 U14_U_logic_C.12 U14_U_logic_D.12 U15_U_logic_A.12 U15_U_logic_B.12 U15_U_logic_C.12 U15_U_logic_D.12 | length 18113.4
  Top Layer w10: v1(3510,5800) U14_U_logic_A.12@3510,5864.64 ; v1(3515,2475) U14_U_logic_D.12@3515,2542.64 ; v1(3515,3595) U14_U_logic_C.12@3515,3662.64 ; v1(3515,4725) U14_U_logic_B.12@3515,4792.64 ; v1(4000,5800) U15_U_logic_A.12@4000,5864.64 ; v1(4005,2475) U15_U_logic_D.12@4005,2542.64 ; v1(4005,3595) U15_U_logic_C.12@4005,3662.64 ; v1(4005,4725) U15_U_logic_B.12@4005,4792.64
  Top Layer w20: v1@2680,6157 2620,6097 2620,5775 v1@2688.59,5706.41 ; v1(2683.9,6153.1) U13_U_logic_A.20@2745,6153.1 ; v1@2685,5085 2630,5030 2630,4703.82 v1(2699.41,4634.41) ; v1@2686.1,3951.1 2635,3900 2635,3568.82 v1(2699.41,3504.41) ; v1(2688.9,3951.1) U13_U_logic_C.20@2750,3951.1 ; v1(2688.9,5081.1) U13_U_logic_B.20@2750,5081.1 ; v1@2695.59,2384.41 2625,2455 2625,2767.2 v1(2688.9,2831.1) U13_U_logic_D.20@2750,2831.1 ; TP5.1@5760,580 U7.3@5760,390 5840,390 5875,355 D3.1@5923.07,355 ; C21.2@5924.88,460 5923.07,458.19 D3.1@5923.07,355 ; D5.2@6056.93,225 6056.93,268.07 6035,290 5950,290 5925,315 5925,353.07 D3.1@5923.07,355
  MidLayer1 w10: v1(2694.41,5706.41) 2694.41,5884.41 2710,5900 3230,5900 3280,5850 3280,5760 3300,5740 3470,5740 3510,5780 ; v1(2699.41,2384.41) 2699.41,2539.41 2730,2570 3260,2570 3300,2530 3300,2445 3355,2390 3490,2390 3515,2415 ; v1(2699.41,3504.41) 2699.41,3664.41 2730,3695 3250,3695 3285,3660 3285,3530 3325,3490 3490,3490 3515,3515 ; v1(2699.41,4634.41) 2699.41,4789.41 2730,4820 3250,4820 3290,4780 3290,4650 3310,4630 3470,4630 3515,4675 ; v1(3510,5800) 3510,5780 ; v1(3515,2475) 3515,2415 ; v1(3515,3595) 3515,3515 ; v1(3515,4725) 3515,4680 3565,4630 3975,4630 4005,4660 v1(4005,4725) ; v1(4000,5800) 4000,5760 3980,5740 3550,5740 3510,5780 ; v1(4005,2475) 4005,2425 3970,2390 3540,2390 3515,2415 ; v1(4005,3595) 4005,3525 3970,3490 3540,3490 3515,3515
  MidLayer1 w20: v1(2688.9,2831.1) 2770,2912.2 2770,3433.82 v1(2699.41,3504.41) ; v1(2688.9,3951.1) 2775,4037.2 2775,4558.82 v1(2699.41,4634.41) ; v1(2688.9,5081.1) 2765,5157.2 2765,5634.8 2694.41,5705.39 v1(2694.41,5706.41)
  Bottom Layer w20: v1@2684.88,6152.12 C33_U_logic_A.2@2745,6152.12 ; v1@2689.88,2830.12 C33_U_logic_D.2@2750,2830.12 ; v1@2689.88,3950.12 C33_U_logic_C.2@2750,3950.12 ; v1@2689.88,5080.12 C33_U_logic_B.2@2750,5080.12 ; v1(2694.41,5706.41) R29_U_logic_A.1@2694.41,5797 ; R29_U_logic_D.1@2699.41,2475 v1(2699.41,2384.41) 2699.41,1530.59 2810,1420 2810,750 2970,590 5560,590 U7.3@5760,390 ; v1(2699.41,3504.41) R29_U_logic_C.1@2699.41,3595 ; v1(2699.41,4634.41) R29_U_logic_B.1@2699.41,4725
WN1: J6.6 OUT1.2 R26_U_diff_out_A.2 | length 4586.3
  Top Layer w15: R26_U_diff_out_A.2@6390.12,1845 6670,1845 6700,1875 6700,2220 6760,2280 7295,2280 7341.5,2233.5 J6.6@8121.81,2233.5
  MidLayer1 w15: OUT1.2@4750,1900 4914,1736 6381,1736 v1(6490,1845)
  Bottom Layer w15: OUT1.2@4750,1900 OUT1.2@4550,1900 OUT1.2@4550,2100 OUT1.2@4750,2100
WN2: J6.7 OUT2.2 R26_U_diff_out_B.2 | length 3739.4
  Top Layer w15: R26_U_diff_out_B.2@7625.12,1845 7795,1845 7815,1865 7815,2000 7939.53,2124.53 J6.7@8121.89,2124.53
  MidLayer1 w15: OUT2.2@5300,1900 7670,1900 v1(7725,1845)
  Bottom Layer w15: OUT2.2@5300,1900 OUT2.2@5100,1900 OUT2.2@5100,2100 OUT2.2@5300,2100
WN3: J6.8 OUT3.2 R26_U_diff_out_C.2 | length 4793.4
  Top Layer w15: R26_U_diff_out_C.2@6385.12,1130 6670,1130 6700,1160 6700,1385 6865,1550 7695,1550 7900,1755 7900,1935 7980.47,2015.47 J6.8@8121.89,2015.47
  MidLayer1 w15: OUT3.2@4750,1200 4927,1023 6378,1023 v1(6485,1130)
  Bottom Layer w15: OUT3.2@4750,1200 OUT3.2@4550,1200 OUT3.2@4550,1400 OUT3.2@4750,1400
WN4: J6.9 OUT4.2 R26_U_diff_out_D.2 | length 4144.5
  Top Layer w15: R26_U_diff_out_D.2@7625.12,1130 7810,1130 7900,1220 7900,1635 8121.89,1856.89 J6.9@8121.89,1906.42
  MidLayer1 w15: OUT4.2@5300,1200 5314.07,1200 5331.07,1183 7672,1183 v1(7725,1130)
  Bottom Layer w15: OUT4.2@5300,1200 OUT4.2@5100,1200 OUT4.2@5100,1400 OUT4.2@5300,1400
WP1: J6.1 OUT1.1 R23_U_diff_out_A.2 | length 3845.7
  Top Layer w15: R23_U_diff_out_A.2@6385.12,2035 v1(6490,2035) 6610,2035 6640,2065 6640,2230 6740,2330 7330,2330 7371.89,2288.11 J6.1@8010.08,2288.11
  MidLayer1 w15: OUT1.1@4650,2000 4855,2000 5047,2192 6333,2192 v1(6490,2035)
WP2: J6.2 OUT2.1 R23_U_diff_out_B.2 | length 2989.1
  Top Layer w15: R23_U_diff_out_B.2@7620.12,2035 v1(7725,2035) 7771.89,2035 7915.94,2179.06 J6.2@8010.08,2179.06
  MidLayer1 w15: OUT2.1@5200,2000 7690,2000 v1(7725,2035)
WP3: J6.3 OUT3.1 R23_U_diff_out_C.2 | length 4066.2
  Top Layer w15: R23_U_diff_out_C.2@6380.12,1320 v1(6485,1320) 6620,1320 6645,1345 6645,1395 6845,1595 7675,1595 7860,1780 7860,1970 7960,2070 J6.3@8010.08,2070
  MidLayer1 w15: OUT3.1@4650,1300 4855,1300 5046,1491 6314,1491 v1(6485,1320)
WP4: J6.4 OUT4.1 R23_U_diff_out_D.2 | length 3508.5
  Top Layer w15: R23_U_diff_out_D.2@7620.12,1320 v1(7725,1320) 7800,1320 7865,1385 7865,1655 7940,1730 7940,1890.87 J6.4@8010.08,1960.94
  MidLayer1 w15: OUT4.1@5200,1300 5406,1300 ; 5407,1299 5489,1217 7622,1217 v1(7725,1320)
pads on no net: J5.5 J6.5 P1.19 P1.38 P1.39 P2.37 P2.38 P2.39 P2.40 P2.41 P2.42 P3.1 P3.19 P3.20 P3.38 P3.39 U1_PZ1_a.1 U1_PZ1_a.8 U1_PZ1_b.1 U1_PZ1_b.8 U1_PZ1_c.1 U1_PZ1_c.8 U1_PZ1_d.1 U1_PZ1_d.8 U1_PZ2_a.1 U1_PZ2_a.8 U1_PZ2_b.1 U1_PZ2_b.8 U1_PZ2_c.1 U1_PZ2_c.8 U1_PZ2_d.1 U1_PZ2_d.8 U1_PZ3_a.1 U1_PZ3_a.8 U1_PZ3_b.1 U1_PZ3_b.8 U1_PZ3_c.1 U1_PZ3_c.8 U1_PZ3_d.1 U1_PZ3_d.8 U2_PZ1_a.7 U2_PZ1_a.8 U2_PZ1_a.14 U2_PZ1_a.15 U2_PZ1_a.16 U2_PZ1_b.7 U2_PZ1_b.8 U2_PZ1_b.14 U2_PZ1_b.15 U2_PZ1_b.16 U2_PZ1_c.7 U2_PZ1_c.8 U2_PZ1_c.14 U2_PZ1_c.15 U2_PZ1_c.16 U2_PZ1_d.7 U2_PZ1_d.8 U2_PZ1_d.14 U2_PZ1_d.15 U2_PZ1_d.16 U2_PZ2_a.7 U2_PZ2_a.8 U2_PZ2_a.14 U2_PZ2_a.15 U2_PZ2_a.16 U2_PZ2_b.7 U2_PZ2_b.8 U2_PZ2_b.14 U2_PZ2_b.15 U2_PZ2_b.16 U2_PZ2_c.7 U2_PZ2_c.8 U2_PZ2_c.14 U2_PZ2_c.15 U2_PZ2_c.16 U2_PZ2_d.7 U2_PZ2_d.8 U2_PZ2_d.14 U2_PZ2_d.15 U2_PZ2_d.16 U2_PZ3_a.7 U2_PZ3_a.8 U2_PZ3_a.14 U2_PZ3_a.15 U2_PZ3_a.16 U2_PZ3_b.7 U2_PZ3_b.8 U2_PZ3_b.14 U2_PZ3_b.15 U2_PZ3_b.16 U2_PZ3_c.7 U2_PZ3_c.8 U2_PZ3_c.14 U2_PZ3_c.15 U2_PZ3_c.16 U2_PZ3_d.7 U2_PZ3_d.8 U2_PZ3_d.14 U2_PZ3_d.15 U2_PZ3_d.16 U3.1 U3.8 U4.1 U4.8 U5.1 U5.8 U6.1 U6.8 U7.2 U8_3dB_a.7 U8_3dB_a.8 U8_3dB_a.14 U8_3dB_a.15 U8_3dB_a.16 U8_3dB_b.7 U8_3dB_b.8 U8_3dB_b.14 U8_3dB_b.15 U8_3dB_b.16 U8_3dB_c.7 U8_3dB_c.8 U8_3dB_c.14 U8_3dB_c.15 U8_3dB_c.16 U8_3dB_d.7 U8_3dB_d.8 U8_3dB_d.14 U8_3dB_d.15 U8_3dB_d.16 U8_6dB_a.7 U8_6dB_a.8 U8_6dB_a.14 U8_6dB_a.15 U8_6dB_a.16 U8_6dB_b.7 U8_6dB_b.8 U8_6dB_b.14 U8_6dB_b.15 U8_6dB_b.16 U8_6dB_c.7 U8_6dB_c.8 U8_6dB_c.14 U8_6dB_c.15 U8_6dB_c.16 U8_6dB_d.7 U8_6dB_d.8 U8_6dB_d.14 U8_6dB_d.15 U8_6dB_d.16 U8_12dB_a.7 U8_12dB_a.8 U8_12dB_a.14 U8_12dB_a.15 U8_12dB_a.16 U8_12dB_b.7 U8_12dB_b.8 U8_12dB_b.14 U8_12dB_b.15 U8_12dB_b.16 U8_12dB_c.7 U8_12dB_c.8 U8_12dB_c.14 U8_12dB_c.15 U8_12dB_c.16 U8_12dB_d.7 U8_12dB_d.8 U8_12dB_d.14 U8_12dB_d.15 U8_12dB_d.16 U8_24dB_a.7 U8_24dB_a.8 U8_24dB_a.14 U8_24dB_a.15 U8_24dB_a.16 U8_24dB_b.7 U8_24dB_b.8 U8_24dB_b.14 U8_24dB_b.15 U8_24dB_b.16 U8_24dB_c.7 U8_24dB_c.8 U8_24dB_c.14 U8_24dB_c.15 U8_24dB_c.16 U8_24dB_d.7 U8_24dB_d.8 U8_24dB_d.14 U8_24dB_d.15 U8_24dB_d.16 U9_3dB_a.1 U9_3dB_a.8 U9_3dB_b.1 U9_3dB_b.8 U9_3dB_c.1 U9_3dB_c.8 U9_3dB_d.1 U9_3dB_d.8 U9_6dB_a.1 U9_6dB_a.8 U9_6dB_b.1 U9_6dB_b.8 U9_6dB_c.1 U9_6dB_c.8 U9_6dB_d.1 U9_6dB_d.8 U9_12dB_a.1 U9_12dB_a.8 U9_12dB_b.1 U9_12dB_b.8 U9_12dB_c.1 U9_12dB_c.8 U9_12dB_d.1 U9_12dB_d.8 U9_24dB_a.1 U9_24dB_a.8 U9_24dB_b.1 U9_24dB_b.8 U9_24dB_c.1 U9_24dB_c.8 U9_24dB_d.1 U9_24dB_d.8 U10_U_diff_in_A.8 U10_U_diff_in_A.9 U10_U_diff_in_B.8 U10_U_diff_in_B.9 U10_U_diff_in_C.8 U10_U_diff_in_C.9 U10_U_diff_in_D.8 U10_U_diff_in_D.9 U13_U_logic_A.9 U13_U_logic_A.12 U13_U_logic_B.9 U13_U_logic_B.12 U13_U_logic_C.9 U13_U_logic_C.12 U13_U_logic_D.9 U13_U_logic_D.12

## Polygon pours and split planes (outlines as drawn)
+15 on InternalPlane1 (split plane): 8419.9,20.1 20.1,20.1 20.1,6979.9 8419.9,6979.9
GND on Internal Plane 3 (split plane): 8419.9,20.1 20.1,20.1 20.1,6979.9 8419.9,6979.9
-15 on InternalPlane2 (split plane): 8419.9,20.1 20.1,20.1 20.1,6979.9 8419.9,6979.9

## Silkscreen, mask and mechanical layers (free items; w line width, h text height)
Top Overlay:
  rectangle: 3426,606 5305,981
  lines w10: 600,5225 600,5135 1725,5135 1725,5880 600,5880 ; 1725,5195 4635,5195 ; 1725,5680 5445,5680 ; 1730,4060 5620,4060 ; 1730,4550 5445,4550 ; 1730,6285 5620,6285 ; 1730,6735 3275,6735 ; 1731,2965 5620,2965 ; 1731,3430 5440,3430 ; 2615,5680 2615,6250 4905,6250 4905,5680 ; 2680,5195 2680,5680 ; 2695,2965 2695,3430 ; 2695,4060 2695,4550 ; 2695,6285 2695,6735 ; 3305,6735 4145,6735 ; 3665,2965 3665,3225 ; 3665,4060 3665,4330 ; 3665,5195 3665,5470 ; 3665,5515 3665,5615 ; 3665,5655 3665,5680 ; 3675,6285 3675,6535 ; 4290,6735 5445,6735 ; 4630,2965 4630,3225 ; 4630,3280 4630,3430 ; 4630,4060 4630,4330 ; 4635,5465 4635,5195 ; 4635,5655 4635,5680 ; 4645,6285 4645,6520 ; 4645,6580 4645,6735 ; 5435,1635 7890,1635 ; 5605,3430 5620,3430 ; 5605,4550 5620,4550 ; 5605,5680 5620,5680 ; 5605,6735 5620,6735 ; 5620,3240 5620,2435 6160,2435 6160,3495 5620,3495 5620,3270 ; 5620,4340 5620,3570 6160,3570 6160,4620 5620,4620 5620,4380 ; 5620,5195 4635,5195 ; 5620,5475 5620,4685 6160,4685 6160,5730 5620,5730 5620,5505 ; 5620,6525 5620,5810 6160,5810 6160,6840 5620,6840 5620,6585 ; 6450,5810 6450,6840 6990,6840 6990,5810 ; 6665,930 6665,2330 ; 6990,3440 6990,2435 6450,2435 6450,3495 6990,3495 6990,3480 ; 6990,4240 6990,3570 6450,3570 6450,4625 6990,4625 6990,4275 ; 6990,5660 6990,4685 6450,4685 6450,5730 6990,5730 6990,5695 ; 7290,3095 7290,2435 7830,2435 ; 7290,3145 7290,3495 7865,3495 7865,2650 ; 7290,3955 7290,3570 7865,3570 7865,3975 ; 7290,4000 7290,4625 7815,4625 ; 7290,4870 7290,4685 7815,4685 ; 7290,4920 7290,5730 7835.02,5730 ; 7830,2335 5435,2335 5435,930 7885,930 ; 7890,935 7890,1655 ; 545,4010 1730,4010 1730,4755 545,4755 545,4010 ; 545,6115 1730,6115 1730,6730 1730,6860 545,6860 545,6115 ; 595,2876 1731,2876 1731,3630 595,3630 595,2876 ; 2610,2335 4905,2335 4905,2935 2610,2935 2610,2335 ; 2615,3450 4905,3450 4905,4030 2615,4030 2615,3450 ; 2615,4580 2615,5170 4905,5170 4905,4580 2615,4580 ; 7290,5795 7865,5795 7865,6845 7290,6845 7290,5795
  text "DIFFERENTIAL RECEIVER" at 535,6885 h60
  text "ZERO POLE FILTER STAGES" at 6040,6880 h60
  text "SWITCHED GAIN STAGES" at 2880,6775 h60
  text "3dB_a" at 4670,6665 h40
  text "PZ1_A" at 5685,6645 h40 r90
  text "PZ2_A" at 6515,6640 h40 r90
  text "24dB_a" at 1745,6635 h40
  text "12dB_a" at 2720,6635 h40
  text "6dB_a" at 3695,6635 h40
  text "PZ3_A" at 7350,6635 h40 r90
  text "GND" at 2145,5910 h40
  text "12dB_b" at 2710,5610 h40
  text "6dB_b" at 3700,5605 h40
  text "3dB_b" at 4655,5605 h40
  text "24dB_b" at 1750,5600 h40
  text "PZ1_B" at 5685,5525 h40 r90
  text "PZ2_B" at 6520,5520 h40 r90
  text "PZ3_B" at 7355,5520 h40 r90
  text "Analog Signal Input" at 570,4930 h60 r90
  text "GND" at 5135,4580 h40
  text "24dB_c" at 1755,4480 h40
  text "12dB_c" at 2720,4475 h40
  text "6dB_c" at 3690,4475 h40
  text "3dB_c" at 4660,4475 h40
  text "PZ1_C" at 5685,4415 h40 r90
  text "PZ2_C" at 6514,4400 h40 r90
  text "PZ3_C" at 7355,4400 h40 r90
  text "Outputs to Binary Input Module" at 7905,4015 h60 r90
  text "GND" at 2190,3730 h40
  text "24dB_d" at 1760,3350 h40
  text "12dB_d" at 2725,3350 h40
  text "6dB_d" at 3705,3350 h40
  text "3dB_d" at 4670,3350 h40
  text "PZ1_D" at 5685,3295 h40 r90
  text "PZ2_D" at 6520,3290 h40 r90
  text "PZ3_D" at 7360,3290 h40 r90
  text "GND" at 5125,2300 h40
  text "Diff_A" at 6390,2260 h40
  text "Diff_B" at 7600,2260 h40
  text "SWITCH LOGIC CIRCUITS" at 3185,2230 h60
  text "In" at 5905,2115 h40
  text "In" at 7145,2115 h40
  text "Out+" at 7691,2083 h40
  text "Out+" at 6455,2080 h40
  text "Out-" at 6484,1702 h40
  text "Out to Anti Alias" at 7930,1690 h60 r90
  text "Out-" at 7590,1657 h40
  text "Diff_D" at 7625,1560 h40
  text "Diff_C" at 6390,1555 h40
  text "In" at 5905,1400 h40
  text "In" at 7150,1400 h40
  text "Out+" at 6450,1365 h40
  text "Out+" at 7685,1365 h40
  text "Serial Number" at 3434,1026 h150
  text "Out-" at 6480,990 h40
  text "Out-" at 7720,985 h40
  text "DIFFERENTIAL DRIVERS" at 6065,840 h60
  text "+15" at 7565,720 h40 r90
  text "Inputs from Binary Output Module" at 645,685 h60 r90
  text "GND" at 7565,575 h40 r90
  text "+5" at 5850,545 h40 r90
  text "+15" at 6430,440 h40 r90
  text "-15" at 7570,400 h40 r90
  text "DC PWR" at 8155,320 h40
  text "GND" at 6430,270 h40 r90
  text "ISC Dewhitening Filter" at 1810,240 h150
  text "-15" at 6430,90 h40 r90
  text "aLIGO D2500133-v1" at 1812,80 h150
Bottom Overlay:
  text "(Alt) Inputs from Binary Output Module" at 745,2655 h60 r90
Mechanical 1:
  the board outline again, w10
Mechanical 13:
  lines w10: -875,5470 318.11,5470 ; -826,1591 430,1591 ; -812,0 82,0 ; 139,0 0,0 1,1 1,6999 426,6999

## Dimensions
-812,0 to -826,1591 on Mechanical 13
-826,1591 to -875,5470 on Mechanical 13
